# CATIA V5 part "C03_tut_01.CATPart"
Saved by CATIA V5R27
Part number: Part1
Bounding box of the stored display mesh (mm): x -1 to 1, y -100 to 100, z -100 to 100
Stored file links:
  E:\_Deepak\2017_Deepak\CATIA\Resources\Tutorial Files\Tutorials\c03_catia_v5_6r2016_tut\C03_tut_01.CATPart
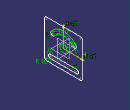
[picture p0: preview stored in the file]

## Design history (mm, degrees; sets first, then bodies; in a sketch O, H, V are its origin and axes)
Body1 (main body)
  Sketch1 on yz-plane, origin (0, 0, 0), H (0, 1, 0), V (0, 0, 1)
    line L1 (100, 90) -> (100, -90)
    line L2 (90, -100) -> (-90, -100)
    line L3 (-100, -90) -> (-100, 90)
    line L4 (-90, 100) -> (90, 100)
    arc A1 centre (-90, 90) radius 10 from (-100, 90) to (-90, 100) cw
    arc A2 centre (90, 90) radius 10 from (90, 100) to (100, 90) cw
    arc A3 centre (90, -90) radius 10 from (90, -100) to (100, -90) ccw
    arc A4 centre (-90, -90) radius 10 from (-90, -100) to (-100, -90) cw
    circle A5 centre (0, 0) radius 20
    construction line L5 (-70, -70) -> (70, -70)
    line L6 (-70, -60) -> (70, -60)
    line L7 (70, -80) -> (-70, -80)
    arc A6 centre (70, -70) radius 10 from (70, -60) to (70, -80) cw
    arc A7 centre (-70, -70) radius 10 from (-70, -80) to (-70, -60) cw
    construction arc A8 centre (0, 0) radius 70 from (57.3406, 40.1504) to (-57.3406, 40.1504) ccw
    construction line L8 (0, 0) -> (57.3406, 40.1504)
    construction line L9 (0, 0) -> (-57.3406, 40.1504)
    arc A9 centre (57.3406, 40.1504) radius 10 from (65.5322, 45.8861) to (49.1491, 34.4146) cw
    arc A10 centre (-57.3406, 40.1504) radius 10 from (-49.1491, 34.4146) to (-65.5322, 45.8861) cw
    arc A11 centre (0, 0) radius 60 from (49.1491, 34.4146) to (-49.1491, 34.4146) ccw
    arc A12 centre (0, 0) radius 80 from (-65.5322, 45.8861) to (65.5322, 45.8861) cw
    radius A1 = 10
    radius A2 = 10
    radius A3 = 10
    radius A4 = 10
    radius A5 = 20
    distance L5 L6 = 10
    radius A8 = 70
    angle L8 L9 = 110
    radius A10 = 10
    vertical: L1 V, L3 V
    horizontal: L2 H, L4 H, L5 H
    equidistance: L1 L3 O, L2 L4 O
    tangency: A1 L3, A1 L4, A2 L4, A2 L1, A3 L2, A3 L1, A4 L2, A4 L3, A6 L6, A7 L6, A6 L7, A7 L7, A11 A10, A10 A12, A12 A9, A9 A11
    concentricity: A11 O, A12 O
